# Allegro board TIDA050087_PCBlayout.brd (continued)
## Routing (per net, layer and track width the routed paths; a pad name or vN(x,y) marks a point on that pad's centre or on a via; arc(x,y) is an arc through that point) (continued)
ADC_IN0: length 19.8
  TOP w0.081: 57.8,44.62 57.23,44.04 57.22,44.04 56.97,43.79 56.97,43.44 U101.B19
  TOP w0.112: v1(57.58,59.33) 57.51,59.33 56.75,58.57 TP413.1 59.66,55.58 59.66,47.8 58.06,46.2 58.06,44.87 57.8,44.62
  BOTTOM w0.112: J802.72 57.48,59.22 v1(57.58,59.33)
ADC_IN1: length 19.8
  TOP w0.112: v1(57.97,59.69) 57.97,58.98 57.82,58.83 TP414.1 57.82,57.91 58.09,57.64 59.19,57.64 59.93,56.91 59.93,47.47 58.3,45.84 58.3,44.77 U101.A20
  BOTTOM w0.112: J802.74 57.88,59.04 57.98,59.14 57.98,59.68 v1(57.97,59.69)
ADC_IN2: length 21.1
  TOP w0.076: 58.18,43.53 58.09,43.44 57.47,43.44 U101.B20
  TOP w0.104: 58.76,44.02 58.67,44.02 58.18,43.53
  TOP w0.112: 58.76,44.02 60.12,44.02 60.87,44.78 60.87,46.57 60.26,47.19 60.26,57.3 TP415.1 58.85,58.71 v1(58.85,59.65)
  BOTTOM w0.112: J802.78 58.68,59.02 58.85,59.19 v1(58.85,59.65)
ADC_IN3: length 20.5
  TOP w0.112: v1(59.25,59.29) 59.41,59.29 TP416.1 60.53,58.17 60.53,47.56 61.35,46.73 61.35,44.67 60.29,43.6 58.7,43.6 58.29,43.2 58.17,43.2 U101.B21
  BOTTOM w0.112: J802.80 59.08,59.13 v1(59.25,59.29)
BB_VSYS_5V: length 76.9
  TOP w0.203: v1(6.46,34.09) 7.11,34.09 7.52,34.5 R911.1
  L3_INT_1 w0.203: v1(6.46,34.09) 6.46,34.17 6.25,34.37 5.57,34.37 4.91,33.72 4.91,6.77 7.67,4.01 10.53,4.01 13.93,0.61 46.73,0.61 v1(48.04,1.91)
  vias: v1(45.12,8.41) v1(45.14,7.88) v1(45.7,8.41) v1(45.7,7.91) v1(46.28,8.41) v1(46.28,7.88) v1(46.84,7.78) v1(60.84,2.47) v1(60.86,3.13) v1(61.5,3.13) v1(61.52,2.47) v1(63.3,3.21) v1(63.28,2.45) v1(64.01,3.18) v1(64.01,2.47) v1(65.22,10.35) v1(65.18,9.71) v1(65.21,9.08) v1(65.73,10.35) v1(65.72,9.74) v1(65.72,9.08) v1(66.24,10.33) v1(66.25,9.74) v1(66.23,9.06)
CLKIN1: length 15.7
  TOP w0.081: 55.97,44.15 55.97,43.44 U101.B17
  TOP w0.112: 55.97,44.15 57.1,45.28 57.1,47.42 57.92,48.23 TP418.1 58,51.37 58,53.7 v1(57.43,54.27) 57.43,54.37 56.85,54.95 R415.1
  BOTTOM w0.112: v1(57.43,54.27) 57.43,54.43 56.68,55.18 J802.67
CLKIN2: length 14.7
  TOP w0.112: U101.A18 56.23,43.7 56.23,44.06 57.34,45.18 57.34,47.14 58.52,48.32 TP419.1 58.35,50.38 58.35,53.96 57.39,54.93 v1(57.39,55.01) 57.55,55.01 R416.1
  BOTTOM w0.112: J802.69 57.08,55.37 57.39,55.06 v1(57.39,55.01)
CLKO01: length 23.8
  TOP w0.112: U101.AA2 48.22,33.33 48.13,33.23 48.13,30.44 47.93,30.24 47.93,13.97 v1(49.25,12.65)
  BOTTOM w0.112: v1(49.25,12.65) 50.4,11.5 J801.79
CLKO02: length 24.4
  TOP w0.081: 48.37,33.1 48.47,33.21 48.47,33.95 U101.Y3
  TOP w0.112: 48.37,33.1 48.37,30.08 48.24,29.95 48.24,14.26 v1(50.25,12.25)
  BOTTOM w0.112: J801.77 50.8,11.7 v1(50.25,12.25)
CLKO03: length 26.6
  TOP w0.081: v1(49.74,35.69) 49.73,35.7 U101.U4
  L3_INT_1 w0.091: v1(49.74,35.69) 49.74,35.65 49.08,34.99
  L3_INT_1 w0.114: v1(50,13.07) 49.45,13.07 49.08,13.44 49.08,34.99
  BOTTOM w0.112: v1(50,13.07) 51.2,11.87 J801.75
CLKO04: length 25.8
  TOP w0.081: v1(49.73,35.18) 49.71,35.2 U101.V4
  L3_INT_1 w0.091: v1(49.73,35.18) 49.41,34.86 49.34,34.83
  L3_INT_1 w0.114: 49.34,34.83 49.34,14.23 v1(49.73,13.84)
  BOTTOM w0.112: J801.73 51.6,12.09 49.85,13.84 v1(49.73,13.84)
CSI_CLK_N: length 16
  TOP w0.086: v1(52.72,42.26) 52.66,42.2 U101.D10
  L3_INT_1 w0.074: v1(51.9,54.19) 51.69,54.41 51.53,54.41 51.41,54.29 51.41,50.2 52.34,49.27 52.34,42.33 52.52,42.16 52.62,42.16 v1(52.72,42.26)
  BOTTOM w0.086: J802.47 52.68,55.63 52.51,55.45 52.51,54.82 51.9,54.22 v1(51.9,54.19)
CSI_CLK_P: length 16.1
  TOP w0.086: v1(52.69,41.73) 52.65,41.7 U101.E10
  L3_INT_1 w0.074: v1(52.69,41.73) 52.54,41.73 52.06,42.22 52.06,49.16 51.13,50.08 51.13,54.4 51.41,54.69 51.45,54.72 v1(51.88,54.72)
  BOTTOM w0.086: v1(51.88,54.72) 52.28,55.12 J802.45
CSI_D0_N: length 14.6
  TOP w0.086: v1(50.7,54.18) 50.84,54.32 51.08,54.32 51.15,54.25 51.15,52.9 53.38,50.67 53.38,45.73 53,45.35 53,44.43 52.81,44.24 52.81,44.23 52.75,44.18 52.75,43.99 52.76,43.99 52.76,43.73 U101.A11
  BOTTOM w0.086: v1(50.7,54.18) 51.12,54.18 51.31,54.37 51.31,55.45 51.48,55.63 J802.41
CSI_D0_P: length 14.6
  TOP w0.076: 52.98,44.09 52.98,43.45 U101.B11
  TOP w0.086: 52.98,44.09 53.22,44.33 53.22,45.26 53.61,45.64 53.61,50.76 51.38,52.99 51.38,54.35 51.01,54.72 v1(50.7,54.72)
  BOTTOM w0.086: J802.39 51.08,55.09 v1(50.7,54.72)
CSI_D1_N: length 14.6
  TOP w0.086: v1(49.53,54.2) 49.58,54.2 49.68,54.29 49.8,54.29 49.96,54.13 49.96,52.99 52.71,50.24 52.71,46.08 52.55,45.92 52.55,44.55 52.3,44.29 52.3,44.04 52.25,44 52.25,43.73 U101.A10
  BOTTOM w0.086: J802.35 50.28,55.63 50.11,55.45 50.11,54.3 50,54.2 v1(49.53,54.2)
CSI_D1_P: length 14.7
  TOP w0.076: U101.B10 52.48,43.45 52.48,43.91 52.53,43.96
  TOP w0.086: v1(49.51,54.73) 49.69,54.73 50.19,54.23 50.19,53.09 52.94,50.33 52.94,45.99 52.78,45.83 52.78,44.45 52.53,44.19 52.53,43.96
  BOTTOM w0.086: v1(49.51,54.73) 49.88,55.1 J802.33
DRAM_CA0_A: length 18.6
  TOP w0.081: U101.H2 47.97,40.45 47.62,40.45 47.45,40.62 47.33,40.62
  TOP w0.091: v1(46.79,40.8) 46.87,40.73 47.22,40.73 47.33,40.62
  TOP w0.104: U201.H2 37.76,41.34 v1(37.76,41.45)
  L3_INT_1 w0.114: v1(37.76,41.45) 38.93,40.28 39.97,40.28 40.07,40.37 40.07,40.64 40.13,40.7 40.31,40.7 40.41,40.61 40.41,40.34 40.5,40.24 40.69,40.24 40.79,40.34 40.79,40.61 40.89,40.7 41.08,40.7 41.18,40.61 41.18,40.34 41.27,40.24 41.47,40.24 41.56,40.34 41.56,40.61 41.66,40.7 41.85,40.7 41.95,40.61 41.95,40.34 42.05,40.24 42.24,40.24 42.34,40.34 42.34,40.61 42.43,40.7 43.23,40.7 43.33,40.61 43.33,40.13 43.42,40.04 43.62,40.04 43.71,40.13 43.71,40.61 43.81,40.7 44,40.7 44.1,40.61 44.1,40.13 44.19,40.04 44.39,40.04 44.48,40.13 44.48,40.61 44.58,40.7 44.77,40.7 44.87,40.61 44.87,40.13 44.97,40.04 45.16,40.04 45.26,40.13 45.26,40.61 45.35,40.7 45.55,40.7 45.64,40.61 45.64,40.13 45.74,40.04 45.93,40.04 46.03,40.13 46.03,40.65 46.18,40.8 v1(46.79,40.8)
DRAM_CA1_A: length 17.6
  TOP w0.081: U101.G1 47.63,40.79 47.4,40.79 47.17,41.02 47.09,41.02 46.66,41.45 v1(46.49,41.45)
  TOP w0.104: v1(37.19,41.45) 37.19,41.43 U201.J2
  L3_INT_1 w0.114: v1(46.49,41.45) 46.2,41.16 45.43,41.16 45.33,41.26 45.33,41.35 45.24,41.45 45.05,41.45 44.95,41.34 44.95,41.26 44.85,41.16 44.66,41.16 44.56,41.26 44.56,41.34 44.46,41.44 44.27,41.44 44.17,41.34 44.17,41.26 44.08,41.16 43.82,41.16 43.72,41.26 43.72,42.29 43.63,42.39 43.43,42.39 43.34,42.29 43.34,41.26 43.24,41.16 42.37,41.16 42.28,41.26 42.28,42.41 42.18,42.51 41.99,42.51 41.89,42.41 41.89,41.26 41.79,41.16 39.46,41.16 38.69,41.93 37.34,41.93 37.19,41.78 v1(37.19,41.45)
DRAM_CA2_A: length 30.8
  TOP w0.081: 46.65,42.32 47.52,41.45 47.97,41.45 U101.F2
  TOP w0.104: U201.H9 37.44,35.45 37.16,35.72 v1(37.16,35.84)
  TOP w0.112: v1(42.46,43.6) 42.59,43.6 42.62,43.57 43.73,43.57 44.43,42.87 45.74,42.87 46.29,42.32 46.65,42.32
  L3_INT_1 w0.114: v1(42.46,43.6) 41.65,43.6 40.51,44.74 38.1,44.74 37.95,44.6 37.95,44.46 38.22,44.19 38.22,44.05 38.08,43.92 37.95,43.92 37.68,44.19 37.54,44.19 37.41,44.05 37.41,43.91 37.68,43.64 37.68,43.51 37.54,43.37 37.4,43.37 37.13,43.64 37,43.64 36.76,43.41 35.75,43.41 35,42.66 35,35.41 35.1,35.32 35.31,35.32 35.41,35.41 35.41,36.69 35.5,36.79 35.7,36.79 35.79,36.69 35.79,35.62 35.89,35.52 36.06,35.52 36.16,35.62 36.16,36.11 36.3,36.25 37.07,36.25 37.16,36.15 v1(37.16,35.84)
DRAM_CA3_A: length 29.4
  TOP w0.104: U201.H10 37.8,34.99 v1(37.8,35.05)
  TOP w0.112: U101.E1 47.57,41.7 46.75,42.51 46.48,42.51 45.84,43.16 44.69,43.16 43.88,43.96 v1(43.39,43.96)
  L3_INT_1 w0.114: v1(43.39,43.96) 42.65,43.96 42.56,44.06 42.56,44.36 42.46,44.46 42.27,44.46 42.17,44.36 42.17,44.06 42.07,43.96 41.78,43.96 40.69,45.05 38,45.05 37.59,44.64 37.46,44.64 37.14,44.96 37,44.96 36.87,44.82 36.87,44.69 37.18,44.37 37.18,44.23 36.64,43.69 35.62,43.69 34.75,42.82 34.75,34.53 34.84,34.43 35.26,34.43 35.35,34.53 35.35,34.65 35.45,34.74 37.49,34.74 v1(37.8,35.05)
DRAM_CA4_A: length 30.3
  TOP w0.081: U101.E2 47.97,41.95 47.58,41.95 46.82,42.71 46.69,42.71
  TOP w0.104: v1(37.77,33.5) 37.77,33.53 U201.H11
  TOP w0.112: v1(43.07,44.75) 43.6,44.75 44.93,43.42 45.98,43.42 46.69,42.71
  L3_INT_1 w0.114: v1(37.77,33.5) 37.35,33.93 34.84,33.93 34.53,34.24 34.53,43.04 35.82,44.34 36.03,44.34 36.4,43.97 36.54,43.97 36.67,44.11 36.67,44.24 36.31,44.61 36.31,44.75 36.99,45.43 40.79,45.43 41.43,44.79 43.03,44.79 v1(43.07,44.75)
DRAM_CA5_A: length 29.3
  TOP w0.104: v1(37.09,33.5) 36.81,33.79 U201.J11
  TOP w0.112: U101.D1 47.59,42.2 46.05,43.74 45.04,43.74 43.53,45.24 v1(42.17,45.24)
  L3_INT_1 w0.114: v1(37.09,33.5) 36.81,33.22 34.51,33.22 34.24,33.49 34.24,43.27 36.73,45.76 40.97,45.76 41.48,45.24 v1(42.17,45.24)
DRAM_CK_C_A: length 25.6
  TOP w0.104: U201.J9 36.81,35.49 36.5,35.81 v1(36.5,35.81)
  TOP w0.117: U101.G5 49.72,40.7 49.72,41.16 v1(49.74,41.18)
  BOTTOM w0.117: v1(36.5,35.81) 36.48,35.8 R205.2 34.93,35.8 34.68,36.05 34.68,41.95 36.43,43.69 41.81,43.69 42.42,43.09 46.3,43.09 47.62,41.76 49.05,41.76 49.06,41.77 49.65,41.18 v1(49.74,41.18)
DRAM_CK_T_A: length 25.6
  TOP w0.104: v1(36.49,36.6) 36.49,36.56 U201.J8
  TOP w0.117: v1(49.22,41.13) 49.28,41.07 49.28,40.75 U101.G4
  BOTTOM w0.117: v1(36.49,36.6) 36.33,36.43 35.89,36.43 R205.1 35.48,36.55 35.36,36.43 35.36,36.14 35.25,36.03 35.03,36.03 34.91,36.14 34.91,41.86 36.52,43.47 41.72,43.47 42.33,42.86 46.2,42.86 47.53,41.54 47.88,41.54 48,41.42 48,41.12 48.08,41.03 48.24,41.03 48.32,41.11 48.32,41.46 48.4,41.54 48.96,41.54 49.22,41.27 v1(49.22,41.13)
DRAM_CKE0_A: length 18.9
  TOP w0.081: v1(47.32,40.3) 47.32,40.28 47.4,40.2 U101.H1
  TOP w0.104: v1(36.44,39.05) 36.44,39.08 U201.J4
  L3_INT_1 w0.114: v1(36.44,39.05) 36.84,39.45 40.73,39.45 41.13,39.05 41.43,39.05 41.52,39.15 41.52,39.74 41.62,39.84 41.81,39.84 41.91,39.74 41.91,39.15 42.01,39.05 42.95,39.05 43.04,39.15 43.04,39.6 43.14,39.7 43.33,39.7 43.43,39.6 43.43,39.15 43.52,39.05 43.72,39.05 43.81,39.15 43.81,39.6 43.91,39.7 44.1,39.7 44.2,39.6 44.2,39.15 44.3,39.05 44.49,39.05 44.59,39.15 44.59,39.6 44.68,39.7 44.91,39.7 45,39.6 45,38.79 45.1,38.7 45.29,38.7 45.39,38.79 45.39,39.6 45.49,39.7 46.13,39.7 46.73,40.3 v1(47.32,40.3)
  BOTTOM w0.112: v1(36.44,39.05) 36.47,39.09 R207.2
DRAM_CKE1_A: length 19.6
  TOP w0.081: v1(49.24,40.25) 49.22,40.24 U101.J4
  TOP w0.104: U201.J5 36.51,38.35 v1(36.51,38.31)
  L3_INT_1 w0.114: v1(49.24,40.25) 48.9,40.59 48.16,40.59 47.38,39.81 46.87,39.81 45.5,38.44 45.15,38.44 45.05,38.35 45.05,37.9 44.96,37.81 44.76,37.81 44.67,37.9 44.67,38.35 44.57,38.44 44.38,38.44 44.28,38.35 44.28,37.9 44.18,37.81 43.99,37.81 43.9,37.9 43.9,38.35 43.8,38.44 43.47,38.44 43.38,38.35 43.38,37.52 43.28,37.43 42.16,37.43 42.06,37.52 42.06,38.57 41.96,38.66 36.86,38.66 v1(36.51,38.31)
  BOTTOM w0.112: v1(36.51,38.31) 36.48,38.29 R208.2
DRAM_DATA0_A: length 10.7
  TOP w0.112: U201.F4 39.07,39.13 39.07,37.85 39.32,37.61 43.16,37.61 TP206.1 44.46,37.93 44.7,37.7 U101.N1
DRAM_DATA1_A: length 10.5
  TOP w0.081: U101.N2 47.97,37.95 47.24,37.95
  TOP w0.112: 47.24,37.95 46.56,37.95 46.44,38.06 44.87,38.06 44.43,38.5 TP209.1 42.91,38.5 42.32,37.9 40.08,37.9 39.74,38.24 39.74,39.11 U201.E4
DRAM_DATA2_A: length 7.5
  TOP w0.112: U201.C4 41.1,39.06 44.42,39.06 45.1,38.38 46.65,38.38 46.83,38.2 U101.M1
DRAM_DATA3_A: length 7.8
  TOP w0.081: 46.75,38.71 47.08,38.38 47.49,38.38 47.56,38.45 47.98,38.45 48.22,38.2 U101.M2
  TOP w0.112: U201.B4 41.76,39.84 42.9,39.84 TP205.1 43.26,39.48 44.64,39.48 45.4,38.71 46.75,38.71
DRAM_DATA4_A: length 7.5
  TOP w0.081: 46.12,39.23 47.69,39.23 U101.K1
  TOP w0.112: 46.12,39.23 44.98,40.37 44.06,40.37 TP207.1 42.97,41.45 41.77,41.45 U201.B2
DRAM_DATA5_A: length 9.7
  TOP w0.081: 47.53,39.45 47.97,39.45 U101.K2
  TOP w0.112: U201.C2 41.03,41.36 41.03,42.07 41.19,42.23 42.97,42.23 TP208.1 44.44,40.76 45.17,40.76 46.49,39.45 47.53,39.45
DRAM_DATA6_A: length 10.7
  TOP w0.112: U201.E2 39.72,41.36 39.72,42.13 40.25,42.66 43.28,42.66 44.79,41.14 45.4,41.14 46.84,39.7 U101.J1
DRAM_DATA7_A: length 12.5
  TOP w0.081: U101.J2 47.97,39.95 47.49,39.95
  TOP w0.104: 40.15,43.12 TP204.1
  TOP w0.112: 40.15,43.12 43.59,43.12 45.09,41.61 45.49,41.61 47.16,39.95 47.49,39.95 ; U201.F2 39.07,41.36 39.07,42.6 39.36,42.88 39.36,42.88 TP204.1
DRAM_DATA8_A: length 10.7
  TOP w0.112: U201.E11 39.72,33.53 39.72,32.76 40.25,32.24 43.28,32.24 44.79,33.75 45.38,33.75 46.83,35.2 U101.V1
DRAM_DATA9_A: length 12.5
  TOP w0.081: U101.V2 47.98,34.95 47.98,34.95 47.49,34.95
  TOP w0.112: U201.F11 39.07,33.53 39.07,32.29 39.59,31.78 TP216.1 43.59,31.78 45.09,33.28 45.44,33.28 47.11,34.95 47.49,34.95
DRAM_DATA10_A: length 9.7
  TOP w0.081: 47.53,35.45 47.98,35.45 47.98,35.45 U101.U2
  TOP w0.112: U201.C11 41.03,33.53 41.03,32.82 41.21,32.64 42.94,32.64 TP215.1 44.44,34.13 45.17,34.13 46.49,35.45 47.53,35.45
DRAM_DATA11_A: length 7.4
  TOP w0.081: U101.U1 47.69,35.67 46.12,35.67
  TOP w0.112: U201.B11 41.74,33.47 43,33.47 TP214.1 44.06,34.53 44.98,34.53 46.12,35.67
DRAM_DATA12_A: length 7.5
  TOP w0.081: U101.R1 46.83,36.7
  TOP w0.112: 46.83,36.7 46.65,36.52 45.13,36.52 44.47,35.86 41.12,35.86 U201.C9
DRAM_DATA13_A: length 7.8
  TOP w0.081: 46.75,36.18 47.08,36.52 47.49,36.52 47.56,36.45 47.98,36.45 48.22,36.69 U101.R2
  TOP w0.112: U201.B9 41.76,35.05 42.9,35.05 TP213.1 43.26,35.42 44.64,35.42 45.4,36.18 46.75,36.18
DRAM_DATA14_A: length 10.5
  TOP w0.081: U101.P2 47.97,36.95 47.24,36.95
  TOP w0.112: 47.24,36.95 46.56,36.95 46.44,36.83 44.87,36.83 44.43,36.39 TP211.1 42.57,36.99 40.08,36.99 39.74,36.65 39.74,35.78 U201.E9
DRAM_DATA15_A: length 10.7
  TOP w0.112: U201.F9 39.07,35.76 39.07,37.04 39.3,37.26 43.19,37.26 TP212.1 44.35,36.96 44.59,37.2 47.46,37.2 U101.P1
DRAM_DMI0_A: length 8.5
  TOP w0.081: 46.85,39.02 47.54,39.02 47.61,38.95 47.97,38.95 U101.L2
  TOP w0.112: U201.C3 41.1,40.64 42.93,40.64 TP201.1 43.63,39.94 44.8,39.94 45.73,39.02 46.85,39.02
DRAM_DMI1_A: length 8.5
  TOP w0.081: U101.T2 48.22,36.19 47.98,35.95 47.61,35.95 47.54,35.88 46.85,35.88
  TOP w0.112: U201.C10 41.11,34.25 42.93,34.25 TP210.1 43.63,34.95 44.8,34.95 45.73,35.88 46.85,35.88
DRAM_NCS0_A: length 24.7
  TOP w0.104: v1(37.15,39.07) 37.16,39.08 37.16,39.15 U201.H4
  TOP w0.112: v1(45.27,42.47) 45.72,42.47 46.11,42.08 46.64,42.08 47.52,41.2 U101.F1
  L3_INT_1 w0.114: v1(45.27,42.47) 44.56,43.19 41.22,43.19 40.83,43.59 40.83,44.02 40.54,44.31 38.88,44.31 37.64,43.07 35.79,43.07 35.24,42.52 35.24,37.76 35.32,37.67 35.87,37.67 36.17,37.38 36.72,37.38 36.81,37.48 36.81,37.77 36.72,37.86 36.28,37.86 36.14,38 36.14,38.64 36.23,38.72 36.59,38.72 36.94,39.07 v1(37.15,39.07)
DRAM_NCS1_A: length 24.9
  TOP w0.081: U101.G2 47.97,40.95 47.47,40.95 47,41.42
  TOP w0.091: 47,41.42 46.59,41.82 v1(45.82,41.82)
  TOP w0.104: U201.H3 37.8,39.91 v1(37.8,39.88)
  L3_INT_1 w0.114: v1(37.8,39.88) 37.1,39.88 37,39.98 37,40.17 36.9,40.27 36.71,40.27 36.61,40.17 36.61,39.79 36.52,39.7 36.32,39.7 36.23,39.79 36.23,40.17 36.13,40.27 35.94,40.27 35.84,40.17 35.84,39.79 35.74,39.7 35.59,39.7 35.49,39.8 35.49,42.39 35.82,42.71 39.23,42.71 39.23,42.72 40.99,42.72 41.1,42.61 41.1,41.92 41.2,41.83 41.39,41.83 41.49,41.92 41.49,42.77 41.58,42.86 42.56,42.86 42.66,42.77 42.66,42.35 42.75,42.25 42.95,42.25 43.04,42.35 43.04,42.77 43.14,42.86 43.99,42.86 44.09,42.77 44.09,41.92 44.19,41.82 44.35,41.82 44.44,41.92 44.44,42.28 44.54,42.38 44.73,42.38 44.83,42.28 44.83,41.92 44.92,41.82 v1(45.82,41.82)
DRAM_NRESET: length 28
  TOP w0.081: U101.D2 47.97,42.45 47.61,42.45 47.32,42.73 47.32,42.85 47.14,43.03
  TOP w0.112: 47.14,43.03 46.16,44.02 45.25,44.02 43.64,45.63 38.54,45.63 34.88,41.97 34.88,33.99 34.35,33.46 v1(32.58,33.46) 32.26,33.78 U201.T11
  BOTTOM w0.112: v1(32.58,33.46) 32.81,33.69 R201.1
DRAM_SDQS0_C_A: length 12.3
  TOP w0.104: U201.E3 39.77,39.88 v1(39.77,39.84)
  TOP w0.117: U101.L4 v1(49.22,39.13)
  BOTTOM w0.117: v1(39.77,39.84) 39.89,39.96 39.89,40.37 40.62,41.1 45.77,41.1 48.05,38.82 48.94,38.82 v1(49.22,39.13)
DRAM_SDQS0_T_A: length 12.2
  TOP w0.104: v1(40.33,39.91) 40.33,39.98 U201.D3
  TOP w0.117: U101.N4 49.22,38.23 v1(49.26,38.27)
  BOTTOM w0.117: v1(40.33,39.91) 40.12,40.11 40.12,40.28 40.25,40.41 40.49,40.41 40.57,40.49 40.57,40.73 40.71,40.87 45.68,40.87 47.96,38.59 49.04,38.59 49.25,38.39 v1(49.26,38.27)
DRAM_SDQS1_C_A: length 12.6
  TOP w0.104: v1(39.75,35.01) 39.75,34.98 U201.E10
  TOP w0.112: U101.R5 49.29,36.27 v1(49.2,36.27)
  BOTTOM w0.117: v1(49.2,36.27) 49.2,36.39 49.03,36.56 45.99,36.56 43.23,33.79 40.73,33.79 40.04,34.49 40.04,34.72 39.75,35.01 v1(39.75,35.01)
DRAM_SDQS1_T_A: length 12.5
  TOP w0.104: U201.D10 40.06,34.68 v1(40.43,35.05)
  TOP w0.117: U101.R4 v1(49.22,37.11)
  BOTTOM w0.117: v1(49.22,37.11) 48.9,36.79 48.35,36.79 48.23,36.91 48.23,37.08 48.12,37.19 47.88,37.19 47.77,37.08 47.77,36.91 47.65,36.79 45.9,36.79 43.13,34.02 40.82,34.02 40.26,34.58 40.26,34.93 40.38,35.05 v1(40.43,35.05)
DRAM_ZN: length 2.5
  TOP w0.081: U101.E4 49.58,41.7 v1(49.6,41.72)
  BOTTOM w0.081: R204.1 49.04,43.17 49.04,42.28 v1(49.6,41.72)
DRAM_ZQ0: length 1.1
  TOP w0.254: v1(42.47,38.62) 42.44,38.58 42.08,38.58 U201.A5
  BOTTOM w0.112: R209.2 42.07,38.98 42.12,38.93 42.2,38.93 42.45,38.68 42.45,38.64 v1(42.47,38.62)
DSI_CLK_N: length 17.9
  TOP w0.086: v1(50.61,42.23) 50.57,42.2 U101.D6
  L3_INT_1 w0.074: v1(50.61,42.23) 50.49,42.23 50.3,42.42 50.3,47.55 44.22,53.63 44.22,53.91 43.93,54.2 43.93,54.65 43.85,54.73 v1(43.48,54.73)
  BOTTOM w0.086: J802.3 43.88,55.42 44,55.3 44.02,55.25 44.02,54.87 43.75,54.6 43.61,54.6 v1(43.48,54.73)
DSI_CLK_P: length 18
  TOP w0.086: U101.E6 50.6,41.7 v1(50.62,41.72)
  L3_INT_1 w0.074: v1(50.62,41.72) 50.39,41.95 50.38,41.95 50.03,42.3 50.03,47.43 43.94,53.51 43.94,53.75 v1(43.5,54.2)
  BOTTOM w0.086: v1(43.5,54.2) 43.67,54.2 44.28,54.81 J802.5
DSI_D0_N: length 16
  TOP w0.081: U101.A6 50.2,43.72 50.2,43.95 50.62,44.37 50.62,47.77 50.35,48.04 50.35,48.04 50.34,48.06
  TOP w0.086: v1(44.69,54.73) 44.85,54.89 45.26,54.89 45.44,54.71 45.44,52.95 50.34,48.06
  BOTTOM w0.086: J802.9 45.08,55.63 45.25,55.45 45.25,55 44.89,54.65 44.77,54.65 v1(44.69,54.73)
DSI_D0_P: length 16
  TOP w0.081: U101.B6 49.97,43.44 49.97,44.04 50.39,44.46 50.39,47.68
  TOP w0.086: v1(44.7,54.2) 45.13,54.2 45.22,54.11 45.22,52.86 50.39,47.68
  BOTTOM w0.086: J802.11 45.48,54.91 44.77,54.2 v1(44.7,54.2)
DSI_D1_N: length 16
  TOP w0.081: U101.A7 50.72,43.93 51.05,44.25 51.05,48.47 50.84,48.69 50.84,48.69 50.79,48.75 50.78,48.75 50.77,48.76
  TOP w0.086: 50.77,48.76 50.08,49.44 49.84,49.44 49.59,49.69 49.59,49.69 49.03,50.26 48.78,50.51 48.78,50.68 48.39,51.07 48.21,51.07 47.96,51.32 47.96,51.56 47.9,51.63 47.65,51.88 47.4,51.88 46.67,52.61 46.67,54.8 46.53,54.94 46.12,54.94 v1(45.9,54.73)
  BOTTOM w0.086: v1(45.9,54.73) 46.11,54.73 46.45,55.07 46.45,55.45 46.28,55.63 J802.15
DSI_D1_P: length 16
  TOP w0.081: U101.B7 50.47,43.45 50.47,43.99 50.83,44.35 50.83,48.38 50.61,48.6
  TOP w0.086: 50.61,48.6 50.61,48.6 49.99,49.21 49.74,49.21 49.36,49.6 48.93,50.03 48.93,50.03 48.55,50.41 48.55,50.58 48.29,50.84 48.12,50.84 47.73,51.22 47.73,51.47 47.55,51.65 47.31,51.65 46.45,52.51 46.45,54.08 46.33,54.2 v1(45.89,54.2)
  BOTTOM w0.086: J802.17 46.68,54.98 45.9,54.2 v1(45.89,54.2)
DSI_D2_N: length 15.9
  TOP w0.081: U101.A8 51.22,43.85 51.49,44.12
  TOP w0.086: 51.49,44.12 51.49,48.87 48.79,51.58 48.79,52.22 48.49,52.52 47.64,52.52 47.37,52.79 47.37,52.95 47.81,53.39 47.81,54.64 47.59,54.86 47.21,54.86 v1(47.08,54.73)
  BOTTOM w0.086: J802.21 47.48,55.63 47.63,55.48 47.63,55.08 47.28,54.73 v1(47.08,54.73)
DSI_D2_P: length 15.9
  TOP w0.076: U101.B8 51.22,43.2 50.97,43.44 50.97,43.95
  TOP w0.081: 50.97,43.95 51.26,44.23
  TOP w0.086: 51.26,44.23 51.26,48.77 48.56,51.48 48.56,52.13 48.39,52.29 47.54,52.29 47.14,52.69 47.14,53.05 47.58,53.49 47.58,53.88 47.26,54.2 v1(47.1,54.2)
  BOTTOM w0.086: v1(47.1,54.2) 47.1,54.23 47.88,55 J802.23
DSI_D3_N: length 16
  TOP w0.081: U101.A9 51.72,43.78
  TOP w0.086: v1(48.31,54.73) 48.48,54.91 48.87,54.91 49.05,54.72 49.05,53.51 48.78,53.24 48.78,53 49.46,52.32 49.46,51.88 49.55,51.79 50.05,51.79 50.27,51.57 50.27,51.06 50.36,50.98 50.87,50.98 51.09,50.76 51.09,50.25 51.17,50.17 51.61,50.17 52.04,49.73 52.04,44.63 51.9,44.48 51.9,43.96 51.72,43.78
  BOTTOM w0.086: v1(48.31,54.73) 48.53,54.73 48.84,55.04 48.84,55.46 48.68,55.63 J802.27
DSI_D3_P: length 15.9
  TOP w0.076: 51.47,43.55 51.47,43.45 U101.B9
  TOP w0.081: 51.47,43.55 51.47,43.84 51.67,44.04
  TOP w0.086: 51.67,44.04 51.67,44.58 51.81,44.72 51.81,49.64 51.52,49.94 51.08,49.94 50.86,50.16 50.86,50.66 50.77,50.75 50.27,50.75 50.05,50.97 50.05,51.48 49.96,51.56 49.45,51.56 49.23,51.78 49.23,52.22 48.55,52.9 48.55,53.33 48.82,53.6 48.82,53.93 48.55,54.2 v1(48.32,54.2)
  BOTTOM w0.086: v1(48.32,54.2) 48.32,54.2 49.08,54.95 J802.29
EMMC_VDDIM: length 3.4
  TOP w0.081: 59.76,22.25 59.76,22.74 v1(59.98,22.96) 60.26,22.68 60.26,22.24 U501.C2 59.76,22.25
  BOTTOM w0.305: C508.1 59.74,23.21 v1(59.98,22.96) 60.38,23.36 C509.1
ENET1_MDC: length 28.5
  TOP w0.112: v1(59.21,12.3) 60,13.09 60,13.74 58.05,15.68 54.38,15.68 52.43,17.64 52.43,32.6 52.72,32.9 U101.AA11
  BOTTOM w0.112: J801.37 58.8,11.89 v1(59.21,12.3)
ENET1_MDIO: length 27.6
  TOP w0.081: 51.95,32.65 52.22,32.92 U101.AA10
  TOP w0.112: v1(58.73,12.93) 58.73,13.85 57.37,15.21 54.18,15.21 51.95,17.44 51.95,32.65
  BOTTOM w0.112: v1(58.73,12.93) 58.4,12.6 J801.39
ENET1_RD0: length 27.1
  TOP w0.081: 51.22,32.95 U101.AA8
  TOP w0.112: v1(57.17,13.06) 57.17,13.32 56.24,14.25 53.79,14.25 50.99,17.04 50.99,32.72 51.22,32.95 51.22,32.95
  BOTTOM w0.112: J801.49 56.4,11.79 56.81,12.2 56.81,12.7 v1(57.17,13.06)
ENET1_RD1: length 27.7
  TOP w0.081: 51.23,32.69 51.47,32.92 51.47,33.94 U101.Y9
  TOP w0.112: v1(57.19,12.28) 57.57,12.66 57.57,13.26 56.34,14.49 53.88,14.49 51.23,17.14 51.23,32.69
  BOTTOM w0.112: J801.47 56.8,11.85 57.19,12.25 v1(57.19,12.28)
ENET1_RD2: length 27
  TOP w0.081: U101.AA9 51.72,32.92 51.47,32.67
  TOP w0.112: v1(57.96,12.86) 57.96,13.21 56.44,14.73 53.98,14.73 51.47,17.24 51.47,32.67
  BOTTOM w0.112: J801.43 57.6,12.5 v1(57.96,12.86)
ENET1_RD3: length 27.7
  TOP w0.081: 51.71,32.52 51.71,32.66 51.97,32.92 51.97,33.95 U101.Y10
  TOP w0.112: v1(58,12.02) 58.34,12.37 58.34,13.17 56.54,14.97 54.08,14.97 51.71,17.34 51.71,32.52
  BOTTOM w0.112: J801.41 v1(58,12.02)
ENET1_RX_CTL: length 27.6
  TOP w0.081: 50.97,33 50.97,33 50.97,33.95 51.22,34.2 U101.Y8
  TOP w0.112: 50.97,33 50.97,32.97 50.76,32.75 50.76,16.94 53.69,14.01 56.14,14.01 56.76,13.39 56.76,12.71 v1(56.31,12.26)
  BOTTOM w0.112: J801.51 56,11.95 v1(56.31,12.26)
ENET1_RXC: length 26.9
  TOP w0.112: U101.AA7 50.71,33.68 50.71,32.98 50.52,32.79 50.52,16.85 53.59,13.77 55.97,13.77 56.37,13.37 v1(56.37,13.09)
  BOTTOM w0.112: v1(56.37,13.09) 55.6,12.32 J801.53
ENET1_TD0: length 32.6
  TOP w0.081: 52.47,32.92 52.47,34.45 U101.W11
  TOP w0.112: 52.47,32.92 52.19,32.63 52.19,17.54 54.28,15.45 57.8,15.45 59.44,13.81 59.44,13.08 58.6,12.23 58.6,10.41 v1(57.33,9.15)
  BOTTOM w0.112: v1(57.33,9.15) 57.6,8.89 J801.44
ENET1_TD1: length 30.7
  TOP w0.081: v1(52.77,36.14) 52.83,36.2 U101.T12
  L3_INT_1 w0.091: v1(52.77,36.14) 52.77,36.13 53.17,35.74 53.17,35.05 52.96,34.85 52.96,32.75 52.88,32.66
  L3_INT_1 w0.114: v1(57.21,10.01) 57.21,10.27 55.6,11.88 55.6,13.08 52.88,15.81 52.88,32.66
  BOTTOM w0.112: J801.42 58,9.22 v1(57.21,10.01)
ENET1_TD2: length 30.3
  TOP w0.081: U101.U12 53.66,35.7 53.71,35.65 v1(53.79,35.65)
  L3_INT_1 w0.091: 53.21,33.95 53.16,34 53.16,34.8 53.39,35.03 53.39,35.24 v1(53.79,35.65)
  L3_INT_1 w0.114: 53.21,33.95 53.21,15.97 55.92,13.26 55.92,11.98 58.4,9.51 v1(58.4,9.35)
  BOTTOM w0.112: J801.40 v1(58.4,9.35)
ENET1_TD3: length 30.1
  TOP w0.081: v1(53.75,35.14) 53.69,35.2 U101.V12
  L3_INT_1 w0.081: v1(53.75,35.14) 53.75,35.1 53.38,34.72 53.38,34.43
  L3_INT_1 w0.091: 53.55,34.25 53.38,34.43
  L3_INT_1 w0.114: 53.55,34.25 53.55,16.46 56.77,13.24 56.77,11.51 57.29,11 57.84,11 v1(58.8,10.04)
  BOTTOM w0.112: J801.38 v1(58.8,10.04)
ENET1_TX_CTL: length 29.4
  TOP w0.081: v1(52.78,35.12) 52.71,35.2 U101.V10
  L3_INT_1 w0.091: 52.62,32.94 52.78,33.1 v1(52.78,35.12)
  L3_INT_1 w0.114: 52.62,32.94 52.62,15.56 54.77,13.41 54.77,11.56 55.96,10.37 v1(56.29,10.37)
  BOTTOM w0.112: J801.48 56.8,9.87 v1(56.29,10.37)
ENET1_TXC: length 30.2
  TOP w0.081: v1(52.77,35.63) 52.7,35.7 U101.U10
  L3_INT_1 w0.091: v1(52.77,35.63) 52.77,35.57 52.45,35.26 52.45,34.99 52.52,34.93 52.52,33.12 52.29,32.89
  L3_INT_1 w0.114: v1(56.4,9.58) 55.18,10.8 54.57,10.8 53.93,11.44 53.93,13.02 52.29,14.66 52.29,32.89
  BOTTOM w0.112: J801.50 v1(56.4,9.58)
ENET2_MDC: length 29.6
  TOP w0.081: 50.47,33.04 50.47,33.95 U101.Y7
  TOP w0.112: v1(55.6,9.44) 55.6,10.96 55.91,11.28 55.91,12.93 55.31,13.54 53.49,13.54 50.28,16.75 50.28,32.84 50.47,33.04
  BOTTOM w0.112: v1(55.6,9.44) J801.54
ENET2_MDIO: length 29.2
  TOP w0.081: U101.AA6 50.22,33.06 50.21,33.05
  TOP w0.112: v1(54.92,10.07) 54.92,10.85 55.62,11.54 55.62,12.89 55.21,13.3 53.39,13.3 50.04,16.65 50.04,32.88 50.21,33.05
  BOTTOM w0.112: v1(54.92,10.07) 54.92,9.52 55.2,9.25 J801.56
ENET2_RD0: length 24.8
  TOP w0.112: U101.AA4 49.22,33.15 49.08,33.02 49.08,16.23 53.14,12.17 v1(53.54,12.17)
  BOTTOM w0.112: v1(53.54,12.17) 53.6,12.12 J801.63
ENET2_RD1: length 26.2
  TOP w0.081: 49.47,33.15 49.47,33.95 U101.Y5
  TOP w0.112: 49.47,33.15 49.47,33.13 49.32,32.98 49.32,16.33 53.08,12.57 54.15,12.57 v1(54.36,12.37)
  BOTTOM w0.112: v1(54.36,12.37) 54.36,12.33 53.98,11.96 53.98,11.7 54,11.68 J801.61
ENET2_RD2: length 25.8
  TOP w0.112: U101.AA5 49.72,33.11 49.56,32.95 49.56,16.45 53.19,12.82 54.51,12.82 54.76,12.57 54.76,12.19 v1(54.37,11.8)
  BOTTOM w0.112: v1(54.37,11.8) 54.4,11.77 J801.59
ENET2_RD3: length 26.7
  TOP w0.081: 49.97,33.08 49.97,33.94 U101.Y6
  TOP w0.112: 49.97,33.08 49.8,32.91 49.8,16.55 53.29,13.06 54.87,13.06 55.17,12.77 v1(55.17,12.35)
  BOTTOM w0.112: J801.57 54.8,11.53 54.78,11.54 54.78,12.01 55.13,12.35 v1(55.17,12.35)
ENET2_RX_CTL: length 24.9
  TOP w0.081: 48.85,33.05 48.97,33.18 48.97,33.95 U101.Y4
  TOP w0.112: 48.85,33.05 48.85,15.89 v1(51.94,12.8)
  BOTTOM w0.112: v1(51.94,12.8) 52.8,11.94 J801.67
ENET2_RXC: length 24.7
  TOP w0.112: U101.AA3 48.72,33.2 48.61,33.08 48.61,15.51 50.97,13.15 50.97,12.59 51.36,12.2 v1(51.97,12.2)
  BOTTOM w0.112: J801.69 52.4,11.98 52.18,12.2 v1(51.97,12.2)
ENET2_TD0: length 29.7
  TOP w0.081: v1(50.76,36.19) 50.77,36.2 U101.T8
  L3_INT_1 w0.091: v1(50.76,36.19) 51.18,35.77 51.18,34.25 50.77,33.84
  L3_INT_1 w0.114: 50.77,33.84 50.77,14.5 51.25,14.01 51.25,10.99 v1(52.91,9.33)
  BOTTOM w0.112: v1(52.91,9.33) 52.91,9.31 53.2,9.03 J801.66
ENET2_TD1: length 29.3
  TOP w0.081: v1(51.7,35.64) 51.64,35.7 U101.U8
  L3_INT_1 w0.081: 51.04,33.58 51.4,33.94
  L3_INT_1 w0.091: 51.4,33.94 51.4,35.53 51.54,35.67 51.67,35.67 v1(51.7,35.64)
  L3_INT_1 w0.114: v1(52.75,10.26) 51.55,11.46 51.55,14.15 51.04,14.66 51.04,33.58
  BOTTOM w0.112: v1(52.75,10.26) 53.6,9.41 J801.64
ENET2_TD2: length 29
  TOP w0.081: v1(51.75,35.14) 51.68,35.2 U101.V8
  L3_INT_1 w0.081: 51.7,33.19 52.08,33.57
  L3_INT_1 w0.091: v1(51.75,35.14) 51.79,35.14 51.79,35.13 51.85,35.13 52.08,34.91 52.08,33.57 ; 51.5,32.99 51.7,33.19
  L3_INT_1 w0.114: 51.5,32.99 51.5,14.58 52.46,13.62 52.46,11.31 v1(53.62,10.16)
  BOTTOM w0.112: v1(53.62,10.16) 54.4,9.38 J801.60
ENET2_TD3: length 30.3
  TOP w0.081: U101.T10 51.82,36.2 51.8,36.18 51.7,36.18 v1(51.67,36.15)
  L3_INT_1 w0.091: v1(51.67,36.15) 51.75,36.15 52.24,35.67 52.24,34.98 52.3,34.92 52.3,33.28 51.92,32.9
  L3_INT_1 w0.114: v1(54.8,9.03) 54.37,9.45 54.37,10.33 53.86,10.85 53.4,10.85 52.79,11.46 52.79,13.8 51.92,14.67 51.92,32.9
  BOTTOM w0.112: J801.58 v1(54.8,9.03)
ENET2_TX_CTL: length 28.6
  TOP w0.081: v1(50.78,35.17) 50.76,35.2 U101.V6
  L3_INT_1 w0.091: 50.35,34.74 v1(50.78,35.17)
  L3_INT_1 w0.114: v1(51.71,9.98) 50.91,10.77 50.91,13.84 50.35,14.39 50.35,34.74
  BOTTOM w0.112: v1(51.71,9.98) 52.8,8.88 J801.68
ENET2_TXC: length 29.2
  TOP w0.081: v1(50.79,35.68) 50.78,35.7 U101.U6
  L3_INT_1 w0.091: 50.09,34.98 v1(50.79,35.68)
  L3_INT_1 w0.114: v1(51.98,9.1) 50.65,10.42 50.65,13.52 50.09,14.08 50.09,34.98
  BOTTOM w0.112: J801.70 52.4,8.68 v1(51.98,9.1)
FSC_CTRL_H1: length 75.8
  TOP w0.112: U901.2 45.48,7.02 43.69,5.24 43.69,4.63 v1(42.7,3.64) ; R969.2 21.87,47.36 TP909.1 21.87,45.92 v1(21.4,45.45)
  L3_INT_1 w0.091: v1(42.7,3.64) 42.63,3.64 42.09,4.17 39.99,4.17 37.72,1.91 34.04,1.91 30.79,5.17 23.97,5.17 22.83,6.31 v1(21.16,6.31)
  L3_INT_1 w0.114: v1(21.4,45.45) 19.62,43.66 19.62,33.47 17.58,31.43 17.58,28.07 14.86,25.36 14.86,19.41 17.07,17.2 17.07,16.03 v1(18.45,14.66)
  BOTTOM w0.112: v1(18.45,14.66) 18.57,14.54 18.57,8.9 v1(21.16,6.31)
FSC_CTRL_H2: length 39.5
  TOP w0.112: v1(23.92,48.81) 24.24,48.81 24.35,48.7 24.35,47.49 24.24,47.38 R970.2 23.87,46.37 TP910.1 ; v1(14.8,18.74) 13.97,17.91 U903.5
  L3_INT_1 w0.114: v1(14.8,18.74) 14.61,18.93 14.61,25.58 17.07,28.04 17.07,41.75 20.48,45.16 23.92,48.6 v1(23.92,48.81)
FSC_CTRL_H3: length 68.1
  TOP w0.112: v1(45.4,16.57) 45.42,16.59 45.42,17.26 U906.5 ; v1(22.73,45.91) 23.31,45.33 24.95,45.33 25.27,45.65 TP911.1
  TOP w0.254: TP911.1 25.27,46.99 R972.2
  L3_INT_1 w0.114: v1(22.73,45.91) 22.73,45.3 20.95,43.52 20.95,38.91 20.2,38.16 20.2,32.82 18.07,30.69 18.07,27.82 17.53,27.29 17.53,24.37 16.88,23.72 16.88,23.72 16.64,23.48 16.64,21.27 17.46,20.45 19.54,20.45 22.66,23.58 28.28,23.58 28.68,23.17 29.98,23.17 31.48,21.67 34.68,21.67 35.64,20.71 42.2,20.71 43.82,19.08 45.75,19.08 45.95,18.88 45.95,17.13 v1(45.4,16.57)
FSC_CTRL_H4: length 31.6
  TOP w0.112: v1(19.34,26.76) 19.85,27.27 U908.5 ; v1(28.1,51.13) TP917.1
  TOP w0.254: R1034.2 TP917.1
  L3_INT_1 w0.114: v1(28.1,51.13) 26.48,49.52 26.48,48.56 21.39,43.46 21.39,38.9 20.5,38.01 20.5,31.43 20.71,31.22 20.71,28.71 19.34,27.34 v1(19.34,26.76)
FSC_CTRL_H5: length 52.2
  TOP w0.112: TP918.1 28.28,51.71 v1(28.74,51.25) ; v1(40.29,29.12) 40.63,28.79 40.63,27.02 40.25,26.64 38.88,26.64 38.52,27 U910.5
  TOP w0.254: R1035.2 26.98,52.68 TP918.1
  L3_INT_1 w0.114: v1(40.29,29.12) 39.5,29.91 27.82,29.91 27.21,29.3 23.05,29.3 20.74,31.61 20.74,37.75 21.74,38.75 21.74,43.27 26.77,48.3 26.77,49.17 28.74,51.14 v1(28.74,51.25)
FSC_CTRL_L1: length 4.7
  TOP w0.112: TP961.1 15.14,45.81 17.26,45.81 R960.2
FSC_CTRL_L2: length 2.1
  TOP w0.112: TP962.1 15.67,47.9 16.57,47.9 R962.2
FSC_CTRL_L3: length 2
  TOP w0.112: R963.2 16.53,48.73 15.38,48.73 TP963.1
FSC_CTRL_L4: length 1.4
  TOP w0.112: TP964.1 15.48,51.86 R964.2
FSC_CTRL_L5: length 1.3
  TOP w0.112: TP965.1 16.55,53.97 R966.2
FT_EECLK: length 22.3
  TOP w0.112: v1(30.64,55.19) 31.09,54.74 31.09,54.16 30.02,53.09 30.02,47.05 30.71,46.37 38.73,46.37 39.4,47.03 39.4,47.83 38.93,48.29 R1016.2
  BOTTOM w0.112: v1(30.64,55.19) 30.89,55.19 30.95,55.26 J901.7
FT_EECS: length 10.1
  TOP w0.112: v1(35.48,54.42) 35.48,54.14 36.89,52.73 38.13,52.73 39.45,51.41 39.45,50.52 38.31,49.39 R1018.2
  BOTTOM w0.112: J901.10 34.69,54.86 34.77,54.94 35.11,54.94 35.48,54.56 v1(35.48,54.42)
FT_EEDATA: length 9.4
  TOP w0.112: v1(30.61,54.49) 30.36,54.49 29.72,53.86 29.72,49.28 v1(29.34,48.9) ; R1015.2 30.6,48.66 v1(30.49,48.78)
  L3_INT_1 w0.091: v1(30.49,48.78) 29.95,48.78 29.82,48.9 v1(29.34,48.9)
  BOTTOM w0.112: v1(30.61,54.49) 30.98,54.86 J901.9
FT_IO_NINT: length 24.1
  TOP w0.112: v1(36.11,54.4) 37.63,54.4 TP906.1 ; v1(20.55,55.63) 20.38,55.46 20.38,55.42 R961.1
  BOTTOM w0.112: v1(20.55,55.63) 20.55,55.27 20.53,55.25 20.53,55.09 21.67,53.96 28.82,53.96 29.65,53.13 35.28,53.13 36.11,53.95 v1(36.11,54.4) 36.11,55.44 35.49,56.06 J901.4
FT_IO_NRST: length 18.6
  TOP w0.112: v1(22.75,58.07) 22.71,58.11 D903.1 ; TP907.1 37.61,55.4 v1(35.35,55.4)
  BOTTOM w0.112: v1(35.35,55.4) 35.1,55.66 J901.6 33.47,55.66 32.98,56.15 32.98,56.95 32.2,57.72 23.1,57.72 v1(22.75,58.07)
FT_IOEXP1_SCL: length 1.8
  TOP w0.112: R968.2 21.63,53.76 U909.15
FT_IOEXP1_SDA: length 2.1
  TOP w0.112: R965.2 22.13,53.17 U909.14
FT_SCL: length 144.3
  TOP w0.112: R926.2 v1(2.14,51.6) 2.14,46.34 1.4,45.6 1.4,40.07 1.99,39.48 R906.2 2.22,35.24 1.35,34.37 1.35,26.91 1.93,26.32 R988.2 2.34,21.29 1.17,20.12 1.17,20.12 1.17,12.44 1.17,12.42 1.2,12.38 1.78,11.8 1.78,8.16 1.28,7.66 1.28,7.65 1.28,7.65 v1(1.28,2.42) 1.9,1.79 3.06,1.79 3.4,2.13 R1033.1 ; R946.2 14.6,39.29 14.22,39.67 14.22,52.99 v1(14.64,53.41) 14.64,55.25 15.2,55.8 15.2,58.75 16.18,59.73 19.89,59.73 21.04,58.59 21.04,56.52 21.93,55.63 v1(21.98,55.63) 22.18,55.43 R968.1 ; R1019.2 2.47,12.78 2.55,12.71 v1(2.55,12.58) ; v1(32.26,55.76) 31.77,56.25 31.77,56.67 32.13,57.03 35.52,57.03 TP904.1
  L3_INT_1 w0.091: v1(2.55,12.58) 1.78,12.58 1.45,12.25 1.45,8.11 1.28,7.94 v1(1.28,2.42)
  BOTTOM w0.112: v1(2.14,51.6) 1.53,52.2 1.53,55.4 3.19,57.07 3.19,59.33 3.69,59.82 7.35,59.82 11.72,55.46 12.6,55.46 v1(14.64,53.41) ; J901.3 31.96,56.06 v1(32.26,55.76) 32.64,55.37 32.64,53.99 32.02,53.37 29.97,53.37 28.99,54.36 23.2,54.36 21.98,55.58 v1(21.98,55.63)
FT_SDA: length 128
  TOP w0.112: v1(4.26,35.58) 4.26,36.14 R910.2 ; R965.1 v1(23.29,55.67) 22.98,55.99 22.17,55.99 22.14,56.02 22.04,56.02 21.37,56.69 21.37,58.77 20.13,60 13.9,60 12.43,58.53 8.62,58.53 7.31,59.84 2.69,59.84 v1(2.26,59.41) ; v1(4.26,22.61) 4.26,22.71 R990.2 ; v1(4.48,9.04) 4.48,9.28 4.61,9.41 R1021.2 ; v1(3.72,49.19) 4.23,49.19 R928.2 ; TP905.1 33.4,57.31 32,57.31 v1(30.04,55.36) ; R948.2 v1(17.48,36.13) ; R1032.1 2.27,2.25 2.28,2.24 v1(2.28,2.19)
  L3_INT_1 w0.091: v1(4.48,9.04) 4.48,22.39 v1(4.26,22.61)
  L3_INT_1 w0.114: v1(2.26,59.41) 3.72,57.94 v1(3.72,49.19) 4.26,48.65 v1(4.26,35.58) v1(4.26,22.61) ; v1(4.48,9.04) 4.48,8.33 2.93,6.77 2.93,2.84 v1(2.28,2.19)
  BOTTOM w0.112: J901.5 30.34,55.66 v1(30.04,55.36) 29.96,55.28 23.69,55.28 v1(23.29,55.67) 22.52,56.45 20.66,56.45 17.29,53.08 17.29,36.32 v1(17.48,36.13)
GPIO_IO00: length 15.9
  TOP w0.112: U101.J21 65.54,39.7 66.11,39.12 68.42,39.12 68.73,39.43 70.43,39.43 70.78,39.78 v1(71.25,39.78)
  BOTTOM w0.112: J803.22 70.44,39.44 70.78,39.78 v1(71.25,39.78)
GPIO_IO01: length 12.8
  TOP w0.081: 58.42,39.44 57.48,39.44 U101.J20
  TOP w0.112: 58.42,39.44 64.47,39.44 65.1,38.81 68.66,38.81 v1(68.89,39.04)
  BOTTOM w0.112: J803.24 v1(68.89,39.04)
GPIO_IO02: length 16.5
  TOP w0.081: U101.K20 57.47,38.95 58.51,38.95
  TOP w0.112: v1(71.18,39) 71.14,39 70.48,38.34 64.74,38.34 64.13,38.95 58.51,38.95
  BOTTOM w0.112: v1(71.18,39) 71.07,39 70.32,38.24 J803.28
GPIO_IO03: length 13.9
  TOP w0.112: v1(70.23,39) 69.8,38.57 64.97,38.57 64.35,39.2 U101.K21
  BOTTOM w0.112: v1(70.23,39) 70.23,38.82 70.06,38.64 J803.26
GPIO_IO04: length 17.2
  TOP w0.091: U101.L17 55.72,38.23 v1(55.71,38.22)
  L3_INT_1 w0.114: v1(55.71,38.22) 55.71,38.09 56.22,37.58 64.05,37.58 65.15,38.68 67.87,38.68 68.46,39.27 68.46,39.5 68.71,39.76 v1(68.71,39.82)
  BOTTOM w0.112: v1(68.71,39.82) 68.71,39.63 68.12,39.04 J803.23
GPIO_IO05: length 14.6
  TOP w0.091: v1(56.21,38.17) 56.22,38.18 56.22,38.25 56.22,38.26 U101.L18
  L3_INT_1 w0.114: v1(56.21,38.17) 56.51,37.88 63.96,37.88 65.21,39.13 67.58,39.13 v1(68.08,39.63)
  BOTTOM w0.112: J803.21 67.21,39.44 67.28,39.37 67.82,39.37 v1(68.08,39.63)
GPIO_IO06: length 10.4
  TOP w0.081: U101.L20 57.47,38.45 58.45,38.45
  TOP w0.112: v1(65.58,37.86) 65.23,37.51 61.93,37.51 60.99,38.45 58.45,38.45
  BOTTOM w0.112: v1(65.58,37.86) 65.96,38.24 J803.27
GPIO_IO07: length 11.9
  TOP w0.112: v1(65.05,37.9) 63.61,37.9 63.47,38.04 63.47,38.49 63.37,38.59 63.1,38.59 63.02,38.51 63.02,38.01 62.9,37.9 62.75,37.9 62.63,38.01 62.63,38.45 62.52,38.57 62.34,38.57 62.23,38.45 62.23,38.01 62.12,37.9 61.94,37.9 61.14,38.7 U101.L21
  BOTTOM w0.112: v1(65.05,37.9) 65.79,38.64 J803.25
GPIO_IO08: length 13.7
  TOP w0.081: 58.46,37.95 57.47,37.95 U101.M20
  TOP w0.112: 58.46,37.95 60.73,37.95 61.64,37.04 67.89,37.04 68.14,37.28 v1(68.14,37.84)
  BOTTOM w0.112: v1(68.14,37.84) 68.14,37.84 67.34,37.04 J803.33
GPIO_IO09: length 11.4
  TOP w0.081: U101.M21 58.76,38.2
  TOP w0.112: v1(67.58,37.83) 67.02,37.27 61.74,37.27 60.82,38.2 58.76,38.2
  BOTTOM w0.112: v1(67.58,37.83) 67.19,37.44 J803.31
GPIO_IO10: length 18.2
  TOP w0.091: U101.N17 55.72,37.31 55.7,37.29 55.7,37.2 v1(55.69,37.19)
  L3_INT_1 w0.114: v1(55.69,37.19) 56.29,36.59 63.9,36.59 64.42,37.11 70.58,37.11 70.9,37.44 v1(71.05,37.44)
  BOTTOM w0.112: v1(71.05,37.44) 70.66,37.04 J803.34
GPIO_IO11: length 18.1
  TOP w0.091: v1(56.19,37.23) 56.19,37.67 U101.N18
  L3_INT_1 w0.114: v1(56.19,37.23) 56.56,36.86 63.76,36.86 64.27,37.37 70.31,37.37 v1(71.14,38.2)
  BOTTOM w0.112: J803.32 70.38,37.44 v1(71.14,38.2)
GPIO_IO12: length 10.9
  TOP w0.081: 58.33,37.44 57.48,37.44 U101.N20
  TOP w0.112: 58.33,37.44 60.4,37.44 61.28,36.56 65.51,36.56 65.62,36.45 v1(65.62,35.86)
  BOTTOM w0.112: v1(65.62,35.86) 66,36.24 J803.37
GPIO_IO13: length 14.6
  TOP w0.112: U101.N21 60.48,37.7 61.38,36.8 68.45,36.8 68.67,37.02 68.67,37.82 v1(68.68,37.82)
  BOTTOM w0.112: J803.35 67.5,36.64 v1(68.68,37.82)
GPIO_IO14: length 14.1
  TOP w0.081: U101.P20 57.48,36.94 58.05,36.94
  TOP w0.112: 58.05,36.94 60.22,36.94 61.71,35.46 66.31,35.46 67.34,36.48 68.46,36.48 68.71,36.23 v1(68.71,35.93)
  BOTTOM w0.112: v1(68.71,35.93) 68.77,35.87 68.77,35.71 69.04,35.44 J803.42
GPIO_IO15: length 12.3
  TOP w0.081: U101.P21 58.76,37.2
  TOP w0.112: v1(65.04,35.88) 65.04,35.98 64.7,36.32 64.16,36.32 64.04,36.21 64.04,35.9 63.93,35.78 63.71,35.78 63.6,35.9 63.6,36.21 63.48,36.32 63.26,36.32 63.15,36.21 63.15,35.9 63.04,35.78 62.81,35.78 62.7,35.9 62.7,36.21 62.59,36.32 62.37,36.32 62.26,36.21 62.26,35.9 62.14,35.78 61.92,35.78 61.81,35.9 61.81,36.21 61.7,36.32 61.18,36.32 60.31,37.2 58.76,37.2
  BOTTOM w0.112: v1(65.04,35.88) 65.04,35.88 65.48,35.44 J803.41
GPIO_IO16: length 11.5
  TOP w0.112: U101.R21 60.13,36.7 61.61,35.22 67.34,35.22 v1(67.56,35.44)
  BOTTOM w0.112: J803.43 67.17,35.04 v1(67.56,35.44)
GPIO_IO17: length 13.1
  TOP w0.081: U101.R20 57.47,36.45 58.51,36.45
  TOP w0.112: v1(68.71,35.14) 68.56,34.98 61.51,34.98 60.04,36.45 58.51,36.45
  BOTTOM w0.112: v1(68.71,35.14) 68.8,35.04 J803.44
GPIO_IO18: length 15.8
  TOP w0.091: U101.R18 56.22,36.31 v1(56.17,36.25)
  L3_INT_1 w0.114: v1(56.17,36.25) 56.58,35.84 56.92,35.84 57.21,36.13 63.95,36.13 64.63,36.8 69.55,36.8 69.7,36.66 v1(70.22,36.66)
  BOTTOM w0.112: J803.36 70.2,36.64 v1(70.22,36.66)
GPIO_IO19: length 17.5
  TOP w0.091: U101.R17 55.72,36.33 v1(55.66,36.26)
  L3_INT_1 w0.081: v1(55.66,36.26) 55.7,36.26 56.36,35.61 56.37,35.61
  L3_INT_1 w0.114: 56.37,35.61 64.03,35.61 64.93,36.51 69.2,36.51 69.46,36.25 70.74,36.25 v1(70.74,36.24)
  BOTTOM w0.112: J803.38 v1(70.74,36.24)
GPIO_IO20: length 16.8
  TOP w0.081: U101.T20 57.47,35.95 58.76,35.95
  TOP w0.112: v1(71.23,33.87) 70.59,34.5 61.31,34.5 59.87,35.95 58.76,35.95
  BOTTOM w0.112: J803.48 70.85,34.24 v1(71.23,33.87)
GPIO_IO21: length 15.2
  TOP w0.081: 58.76,36.2 U101.T21
  TOP w0.112: v1(70.78,35.07) 70.45,34.74 61.41,34.74 59.95,36.2 58.76,36.2
  BOTTOM w0.112: v1(70.78,35.07) 70.75,35.07 70.33,34.64 J803.46
GPIO_IO22: length 15.8
  TOP w0.081: v1(56.67,35.27) 56.42,35.52 56.4,35.52 U101.U18
  L3_INT_1 w0.081: v1(56.67,35.27) 57.09,35.27 57.42,34.94
  L3_INT_1 w0.114: 57.42,34.94 68.03,34.94 68.12,35.03 68.12,35.8 67.93,36 v1(67.93,36.08)
  BOTTOM w0.112: v1(67.93,36.08) 67.93,36 68.12,35.8 68.12,35.38 67.38,34.64 J803.45
GPIO_IO23: length 16.7
  TOP w0.081: 58.57,35.45 57.47,35.45 U101.U20
  TOP w0.112: 58.57,35.45 59.69,35.45 61.68,33.46 66.31,33.46 67.12,34.26 70.32,34.26 70.82,33.76 v1(70.82,33.44)
  BOTTOM w0.112: J803.52 v1(70.82,33.44)
GPIO_IO24: length 13.5
  TOP w0.112: v1(65.62,33.85) 65.62,34.15 65.51,34.26 65.14,34.26 65.02,34.15 65.02,33.85 64.91,33.74 64.69,33.74 64.58,33.85 64.58,34.15 64.46,34.26 64.24,34.26 64.13,34.15 64.13,33.85 64.02,33.74 63.79,33.74 63.68,33.85 63.68,34.15 63.57,34.26 63.35,34.26 63.24,34.15 63.24,33.85 63.12,33.74 62.9,33.74 62.79,33.85 62.79,34.15 62.68,34.26 62.45,34.26 62.34,34.15 62.34,33.85 62.23,33.74 62.01,33.74 61.89,33.85 61.89,34.15 61.78,34.26 61.21,34.26 59.78,35.7 U101.U21
  BOTTOM w0.112: J803.47 65.82,34.24 65.62,34.04 v1(65.62,33.85)
GPIO_IO25: length 11.9
  TOP w0.081: U101.V21 58.76,35.2
  TOP w0.112: 58.76,35.2 59.6,35.2 61.58,33.22 67.18,33.22 67.54,33.57 v1(67.54,33.83)
  BOTTOM w0.112: v1(67.54,33.83) 67.16,33.44 J803.51
GPIO_IO26: length 14.5
  TOP w0.081: U101.V20 57.47,34.95 58.54,34.95
  TOP w0.112: 58.54,34.95 58.55,34.96 59.5,34.96 61.48,32.98 67.65,32.98 v1(68.48,33.81)
  BOTTOM w0.112: v1(68.48,33.81) 67.71,33.04 J803.53
GPIO_IO27: length 12.8
  TOP w0.112: v1(68.76,33.04) 68.33,33.04 68.03,32.74 61.38,32.74 59.4,34.72 57.75,34.72 U101.W21
  BOTTOM w0.112: J803.54 v1(68.76,33.04)
GPIO_IO28: length 15
  TOP w0.081: U101.W20 57.47,34.45 58.76,34.45
  TOP w0.112: 58.76,34.45 59.34,34.45 61.28,32.5 69.79,32.5 v1(70.24,32.95)
  BOTTOM w0.112: J803.56 70.01,32.64 70.24,32.87 v1(70.24,32.95)
GPIO_IO29: length 16.5
  TOP w0.081: U101.Y21 57.98,33.94 58.76,33.94
  TOP w0.112: 58.76,33.94 59.5,33.94 61.18,32.26 70.85,32.26 v1(71.28,32.7)
  BOTTOM w0.112: J803.58 69.54,32.27 70.68,32.27 71.11,32.7 v1(71.28,32.7)
I2C1_SCL: length 86.5
  TOP w0.076: 57.84,42.44 57.48,42.44 U101.C20
  TOP w0.112: R307.2 71.71,46.19 69.96,44.45 69.28,44.45 v1(69.1,44.63) 68.43,45.3 63.17,45.3 60.61,42.74 59.63,42.74 59.34,42.44 57.84,42.44 ; v1(44.43,13.85) 41.15,10.57 v1(39.87,10.57)
  BOTTOM w0.112: J803.4 69.11,43.04 68.97,43.19 68.97,44.49 v1(69.1,44.63) 69.1,44.89 69.43,45.22 70.98,45.22 72.92,43.28 72.92,18.5 69.95,15.53 46.11,15.53 v1(44.43,13.85) ; v1(39.87,10.57) 39.54,10.9 R717.2
I2C1_SDA: length 88.1
  TOP w0.112: R306.2 70.63,45.46 70.01,44.84 v1(69.64,44.84) 69.44,44.84 68.74,45.53 63.07,45.53 60.52,42.99 59.55,42.99 59.25,42.7 U101.C21
  BOTTOM w0.112: R719.2 35.01,10.47 39.33,14.79 44.84,14.79 45.85,15.81 69.9,15.81 72.68,18.6 72.68,43.18 70.88,44.98 69.79,44.98 v1(69.64,44.84) 69.64,44.59 70.06,44.17 70.06,43.67 69.84,43.44 69.52,43.44 J803.2
I2C2_SCL: length 89.3
  TOP w0.081: U101.D20 57.47,41.95 58.56,41.95
  TOP w0.112: v1(68.34,46.08) R309.2 ; v1(37.69,21.79) 37.69,21.84 37.16,22.37 33.65,22.37 32.72,23.3 30.54,23.3 29.98,22.73 29.98,22.17 R714.2 ; 58.56,41.95 59.75,41.95 59.79,41.91 60.11,41.91 60.15,41.95 60.32,41.95 60.66,42.29 v1(60.66,42.35)
  L3_INT_1 w0.114: v1(60.66,42.35) 61.02,42.71 65.98,42.71 v1(67.85,44.58) 67.85,45.59 v1(68.34,46.08)
  BOTTOM w0.112: v1(37.69,21.79) 37.53,21.62 37.53,20.69 40.73,17.48 69.06,17.48 71.68,20.1 71.68,33.96 71.16,34.48 71.16,36.28 71.68,36.8 71.68,41.99 71.43,42.24 J803.8 69.12,42.24 67.85,43.51 v1(67.85,44.58)
I2C2_SDA: length 89.3
  TOP w0.112: R308.2 v1(69.4,46.12) ; v1(37.09,21.85) 36.81,22.13 33.55,22.13 32.62,23.06 30.64,23.06 30.26,22.68 30.26,21.99 R715.2 ; U101.D21 59.85,42.2 v1(59.95,42.3)
  L3_INT_1 w0.114: v1(69.4,46.12) 68.42,45.14 v1(68.42,44.6) 68.42,44.36 66.44,42.38 61.72,42.38 61.21,41.87 60.38,41.87 v1(59.95,42.3)
  BOTTOM w0.112: v1(68.42,44.6) 68.42,43.36 69.13,42.64 J803.6 71.36,42.64 71.92,42.09 71.92,36.6 71.4,36.08 71.4,34.58 71.92,34.06 71.92,20 69.17,17.25 40.62,17.25 37.29,20.59 37.29,21.65 v1(37.09,21.85)
JTAG_TCK: length 29.6
  TOP w0.112: U101.Y1 47.49,33.96 47.38,33.96 46.97,33.55 46.97,33.2 47.62,32.54 47.62,30.86 47.36,30.6 47.36,12.9 48.77,11.49 TP404.1 48.77,10.82 v1(50.02,9.58) R403.1
  BOTTOM w0.112: v1(50.02,9.58) 50.42,9.58 51.2,8.8 J801.76
JTAG_TDI: length 30.5
  TOP w0.112: U101.W1 47.37,34.7 46.39,33.72 46.39,33 47.15,32.24 47.15,31.06 46.86,30.77 46.86,12.64 48.11,11.38 48.11,9.86 TP402.1 48.77,8.9 49.28,8.39 49.64,8.39 v1(50.35,7.67)
  BOTTOM w0.112: v1(50.35,7.67) 50.4,7.72 J801.80
JTAG_TDO: length 28
  TOP w0.081: 47.86,33.21 47.97,33.31 47.97,33.94 U101.Y2
  TOP w0.112: 47.86,33.21 47.86,30.76 47.6,30.5 47.6,13.04 48.45,12.2 TP405.1 50.15,10.83 v1(50.15,10.34)
  BOTTOM w0.112: v1(50.15,10.34) 50.17,10.32 50.22,10.32 51.6,8.95 51.6,8.32 J801.74
JTAG_TMS: length 29.9
  TOP w0.081: U101.W2 47.97,34.45 47.5,34.45 46.9,33.84
  TOP w0.112: v1(49.36,9.02) 49.36,9.58 TP403.1 48.4,10.54 48.4,11.43 47.09,12.74 47.09,30.67 47.39,30.96 47.39,32.38 46.73,33.03 46.73,33.67 46.9,33.84
  BOTTOM w0.112: v1(49.36,9.02) 50.5,9.02 50.8,8.73 J801.78
LPD4/X_VDD1: length 19.7
  TOP w0.203: v1(12.59,15.23) 12.29,15.52 R1006.1
  TOP w0.254: U201.G4 37.78,39.12 v1(37.78,39.09) ; v1(37.8,35.79) 37.8,35.75 U201.G9 ; U201.T4 32.26,39.52 v1(31.93,39.85) ; U201.F12 38.47,32.76 v1(38.47,32.7) ; v1(31.28,32.65) 31.61,32.97 U201.U12 ; U201.T9 32.26,35.37 v1(31.93,35.05) ; U201.U1 31.61,41.92 v1(31.28,42.25) ; v1(38.69,42.32) 38.69,41.92 U201.F1
  BOTTOM w0.203: v1(12.59,15.23) 13.03,15.23 13.54,14.72 13.54,10.4 14.08,9.85 15.61,9.85 16.54,10.79 16.54,11.54 15.93,12.15 15.32,12.15 v1(15.04,11.87)
  BOTTOM w0.254: v1(38.69,42.32) 38.97,42.04 C204.1 ; v1(31.28,42.25) 31.26,42.27 C201.1 ; v1(37.8,35.79) 37.4,35.38 C203.1 ; C205.1 37.99,38.88 v1(37.78,39.09) ; v1(31.93,35.05) 32.15,34.83 C209.1
  vias: v1(14.46,11.85) v1(14.46,11.28) v1(14.47,10.69) v1(15.03,11.29) v1(15.04,10.69) v1(21.34,36.79) v1(21.34,36.23) v1(21.35,35.63) v1(21.91,36.8) v1(21.91,36.23) v1(21.92,35.64) v2(23.58,36.05)
LPD4/X_VDD2: length 30.1
  TOP w0.203: R1026.1 24.95,38.5 25.18,38.28 25.18,33.05 27.2,31.02 27.2,28.85 26.93,28.58 26.41,28.58 26.2,28.8 R1017.2
  TOP w0.254: v1(28.03,39.85) 28.36,39.52 U201.AB4 ; U201.N3 34.21,40.32 v1(33.88,40.65) ; U201.K1 35.91,42.1 v1(35.91,42.29) ; U201.H8 37.28,36.43 v1(37.28,36.66) ; v1(31.28,39.05) 31.61,38.72 U201.U5 ; v1(35.9,40.62) 35.9,40.51 U201.K3 ; v1(32.58,35.85) 32.91,36.17 U201.R8 ; v1(32.58,39.05) 32.91,38.72 U201.R5 ; U201.A4 v1(42.48,39.45) ; v1(33.88,42.25) 34.21,41.92 U201.N1 ; v1(32.58,32.65) 32.91,32.97 U201.R12 ; U201.H5 37.28,38.47 v1(37.28,38.23) ; v1(32.58,42.25) 32.91,41.92 U201.R1 ; v1(38.61,38.21) 38.61,38.5 U201.F5 ; U201.N10 34.21,34.72 v1(33.88,35.05) ; U201.F8 38.61,36.4 38.61,36.64 v1(38.6,36.65) ; U201.H1 37.14,42.16 v1(37.14,42.24) ; U201.K10 v1(35.84,34.33) ; U201.K12 v1(35.81,32.7) ; U201.U8 31.61,36.17 v1(31.28,35.85) ; v1(33.88,32.65) 34.21,32.97 U201.N12 ; v1(42.49,35.44) 42.48,35.45 U201.A9 ; U201.H12 37.13,32.72 v1(37.13,32.69) ; U201.AB9 28.36,35.37 v1(28.03,35.05)
  BOTTOM w0.254: v1(35.91,42.29) 35.91,42.1 36.27,41.74 C211.1 ; v1(32.58,35.85) 32.52,35.91 C213.1 ; v1(32.58,39.05) 32.54,39.01 C210.1 ; v1(33.88,32.65) 33.84,32.6 C212.1 ; C207.1 33.89,42.25 v1(33.88,42.25) ; C208.1 38.63,36.62 v1(38.6,36.65) ; v1(35.81,32.7) 35.77,32.66 C206.1 ; C214.1 38.48,38.08 v1(38.61,38.21) ; R210.1 37.37,42.47 v1(37.14,42.24)
  vias: v1(24.88,30.41) v1(24.89,29.77) v1(25.52,30.4) v1(25.54,29.79) v1(26.16,30.4) v1(26.17,29.79)
LPD4/X_VDD2_1V1: length 28.7
  TOP w0.203: R1022.1 25.51,38.8 25.51,33.18 27.55,31.14 27.55,27.78 26.91,27.14 26.2,27.14 ; 23.54,27.21 23.54,32.37 22.43,33.48 20.21,33.48 19.95,33.74 19.95,34.45 R949.1
  BOTTOM w0.203: R1093.2 21.93,11.82 v1(21.27,11.16)
  vias: v1(20.63,25.76) v1(21.42,25.76) v1(22,10.46) v1(22.05,9.96) v1(22.51,10.42) v1(22.59,9.89) v1(22.82,11.08) v1(23.15,25.71) v1(23.93,25.74) v1(25.69,25.76)
LPD4/X_VDDQ: length 53.3
  TOP w0.203: U201.F10 39.03,34.92 v1(39.03,35.02) ; U201.D1 40.36,41.55 40.36,41.52 v1(40.38,41.49) ; v1(28.1,29.26) 28.76,29.26 29.17,28.86 R1007.2 ; U201.B10 41.05,34.96 41.05,35.05 v1(41.04,35.05) ; R923.1 11.87,54.53 v1(12.15,54.53) ; U201.D12 40.38,33.36 v1(40.38,33.4)
  TOP w0.254: U201.W1 30.31,41.92 v1(29.98,42.25) ; U201.W12 30.31,32.97 v1(29.98,32.65) ; U201.D5 40.38,38.33 v1(40.38,38.3) ; U201.U3 31.61,40.32 v1(31.28,40.65) ; v1(28.68,35.85) 29.01,36.17 U201.AA8 ; U201.W5 30.31,38.72 v1(29.98,39.05) ; U201.B3 41.02,39.91 v1(41.02,39.88) ; v1(41.64,36.57) 41.64,36.53 U201.B8 ; v1(28.68,34.25) 29.01,34.57 U201.AA10 ; v1(39.06,39.92) 39.06,39.95 U201.F3 ; U201.AA5 29.01,38.72 v1(28.68,39.05) ; v1(41.61,38.3) 41.61,38.39 U201.B5 ; v1(29.98,35.85) 30.31,36.17 U201.W8 ; U201.AA3 29.01,40.32 v1(28.68,40.65) ; U201.D8 40.36,36.55 v1(40.36,36.62) ; v1(31.28,34.25) 31.61,34.57 U201.U10
  BOTTOM w0.203: v1(28.1,29.26) 23.16,29.26 16.21,36.21 16.21,51.1 12.79,54.53 v1(12.15,54.53)
  BOTTOM w0.254: v1(40.38,41.49) 40.43,41.54 C216.1 ; C221.1 38.98,40 v1(39.06,39.92) ; C218.1 41.4,34.7 41.05,35.05 v1(41.04,35.05) ; C215.1 29.93,42.3 v1(29.98,42.25) ; R209.1 41.49,38.42 v1(41.61,38.3) ; v1(40.38,38.3) 40.46,38.21 C217.1 ; v1(29.98,32.65) 29.95,32.62 C222.1 ; C219.1 28.62,40.71 v1(28.68,40.65) ; v1(29.98,35.85) 29.94,35.89 C220.1
  BOTTOM w0.305: v1(41.64,36.57) 41.68,36.54 R211.1
  vias: v1(29.06,30.6) v1(29.62,30.59) v1(30.42,30.59) v1(30.98,30.59)
LPD4/X_VDDQ_0V6: length 56.2
  TOP w0.203: 27.99,26.96 28.05,27.02 v1(28.05,28.63) ; 32.37,27.22 32.37,27.69 31.54,28.51 31.54,30.96 30.87,31.64 28.14,31.64 26.58,33.2 26.58,39.4 25.29,40.69 R941.1 ; v1(12.1,53.98) 11.48,53.98 R921.1
  BOTTOM w0.203: v1(28.05,28.63) 27.98,28.63 27.68,28.93 23.02,28.93 15.88,36.07 15.88,50.91 12.78,54.01 12.13,54.01 v1(12.1,53.98)
LVDS_CLK_N: length 28.1
  TOP w0.081: 49.04,46.53 49.31,46.26 49.31,44.78 48.72,44.19 48.72,43.97
  TOP w0.086: 49.04,46.53 45.63,49.94 42.53,49.94 41.54,50.94 41.54,56.01 42.59,57.06 45.48,57.06 46.56,58.14 46.56,59.73 45.93,60.36 v1(45.87,60.36) ; U101.A3 48.72,43.97
  BOTTOM w0.086: v1(45.87,60.36) 46.68,59.55 J802.18
LVDS_CLK_P: length 28.1
  TOP w0.081: U101.B3 48.48,43.44 48.48,43.93 48.5,43.96 48.5,44.29 49.08,44.87 49.08,46.17 48.95,46.3 48.95,46.3 48.9,46.35 48.89,46.35 48.88,46.37
  TOP w0.086: v1(45.86,59.83) 45.99,59.83 46,59.84 46.13,59.84 46.33,59.64 46.33,59.21 46.01,58.89 46.01,58.77 46.33,58.45 46.33,58.23 45.39,57.29 42.5,57.29 41.31,56.1 41.31,50.84 42.44,49.71 45.54,49.71 48.88,46.37
  BOTTOM w0.086: J802.16 46.28,58.94 46.45,59.11 46.45,59.45 46.05,59.86 45.89,59.86 v1(45.86,59.83)
LVDS_TX0_N: length 28.1
  TOP w0.081: U101.A5 49.7,43.72 49.7,43.99 50.19,44.48 50.19,47.31 50.03,47.47
  TOP w0.086: 50.03,47.47 46.13,51.37 43.77,51.37 42.91,52.22 42.91,55.39 43.28,55.77 46.64,55.77 49.01,58.13 49.01,59.65 48.3,60.36 48.28,60.36 v1(48.27,60.37)
  BOTTOM w0.086: v1(48.27,60.37) 49.08,59.57 J802.30
LVDS_TX0_P: length 28.1
  TOP w0.081: U101.B5 49.48,43.44 49.48,44.09 49.96,44.57 49.96,47.21
  TOP w0.086: 49.96,47.21 46.03,51.14 43.67,51.14 42.68,52.13 42.68,55.49 43.19,55.99 46.55,55.99 48.78,58.22 48.78,58.44 48.43,58.79 48.43,58.92 48.78,59.27 48.78,59.56 48.51,59.83 48.29,59.83 v1(48.28,59.84)
  BOTTOM w0.086: J802.28 48.68,58.94 48.85,59.11 48.85,59.47 48.49,59.83 48.29,59.83 v1(48.28,59.84)
